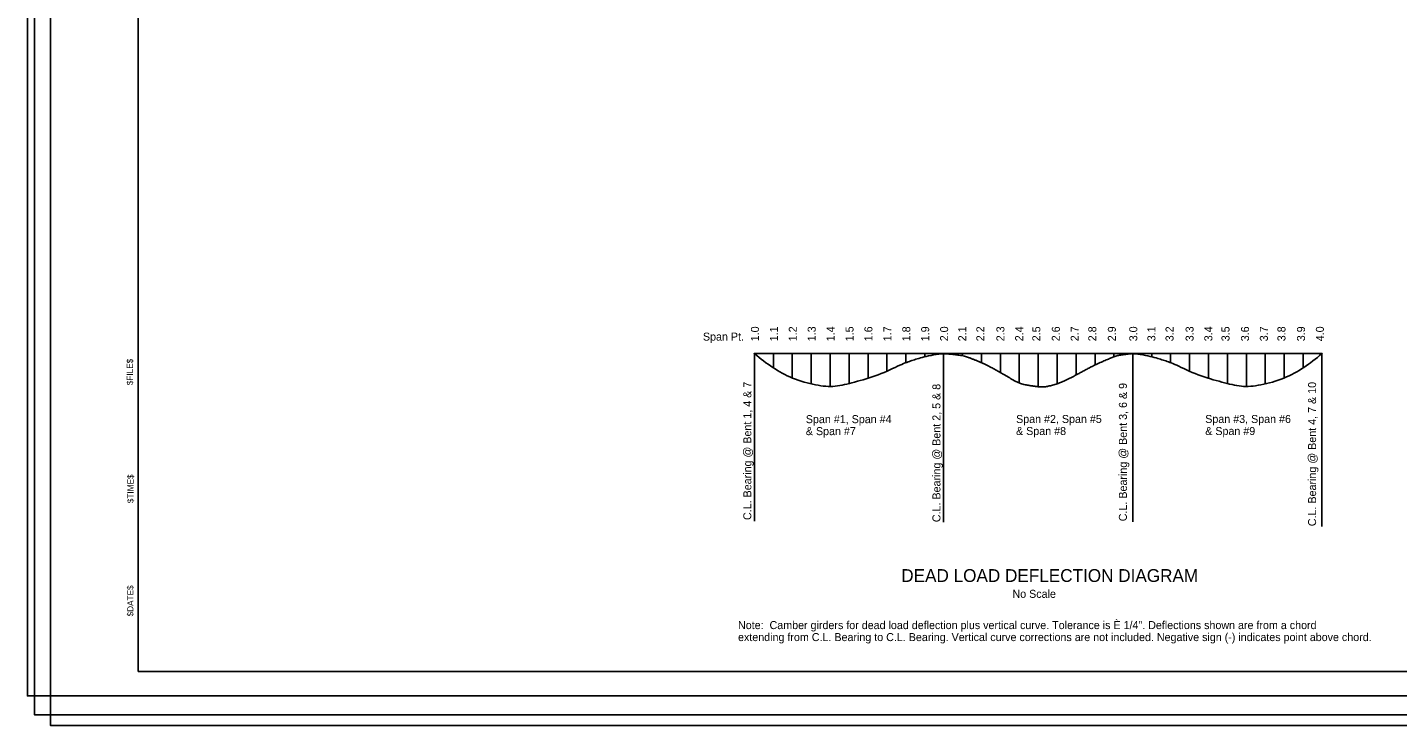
# Model space of a CAD drawing. Extents: x -725.7 to -683.7, y 85.6 to 107.6.
# Drawn here: x -725.67 to -704.28, y 85.62 to 96.51 of the extents above; entities that cross this region are included whole.
import ezdxf

# ---------------------------------------------------------------- set-up
doc = ezdxf.new("R2010")
doc.units = 0
for name, color, linetype in [('border', 7, 'Continuous'), ('Border 2660-Hwy18 - Level 62', 7, 'Continuous'), ('Border 2660-Hwy18 - Level 63', 7, 'Continuous'), ('Dimensions', 7, 'Continuous'), ('Level 20', 7, 'Continuous'), ('Level 25', 7, 'Continuous'), ('Level 40', 7, 'Continuous'), ('Level 41', 7, 'Continuous'), ('Level 62 PDF', 7, 'Continuous')]:
    doc.layers.add(name, color=color, linetype=linetype)

msp = doc.modelspace()

# ---------------------------------------------------------------- linework, layer by layer
at = {"layer": 'border'}
for p, q in [((-723.942, 86.465), (-723.942, 107.01)), ((-691.93, 86.465), (-723.942, 86.465))]:
    msp.add_line(p, q, dxfattribs=at)
at = {"layer": 'Border 2660-Hwy18 - Level 62'}
msp.add_lwpolyline([(-725.562, 107.596), (-691.443, 107.596), (-691.443, 85.786), (-725.562, 85.786)], close=True, dxfattribs=at)
at = {"layer": 'Border 2660-Hwy18 - Level 63'}
msp.add_lwpolyline([(-725.673, 107.453), (-691.673, 107.453), (-691.673, 86.083), (-725.673, 86.083)], close=True, dxfattribs=at)
at = {"layer": 'Dimensions'}
for centre in [(-714.319, 91.424), (-714.023, 91.424), (-713.728, 91.424), (-713.433, 91.424), (-713.137, 91.424), (-712.842, 91.424), (-712.546, 91.424), (-712.251, 91.424), (-711.956, 91.424), (-711.66, 91.424), (-711.365, 91.424), (-711.069, 91.424), (-710.774, 91.424), (-710.478, 91.424), (-710.183, 91.424), (-709.888, 91.424), (-709.592, 91.424), (-709.297, 91.424), (-709.001, 91.424), (-708.706, 91.424), (-708.411, 91.424), (-708.115, 91.424), (-707.82, 91.424), (-707.524, 91.424), (-707.229, 91.424), (-706.934, 91.424), (-706.638, 91.424), (-706.343, 91.424), (-706.047, 91.424), (-705.752, 91.424), (-705.457, 91.424)]:
    msp.add_circle(centre, 0.004, dxfattribs=at)
at = {"layer": 'Level 20'}
for p, q in [((-714.319, 88.808), (-714.319, 91.424)), ((-711.365, 88.793), (-711.365, 91.424)), ((-708.411, 88.8), (-708.411, 91.424)), ((-705.457, 89.939), (-705.457, 91.424)), ((-705.457, 88.728), (-705.457, 91.424))]:
    msp.add_line(p, q, dxfattribs=at)
at = {"layer": 'Level 25'}
for p, q in [((-714.319, 91.424), (-711.365, 91.424)), ((-708.411, 91.424), (-711.365, 91.424)), ((-705.457, 91.424), (-708.411, 91.424))]:
    msp.add_line(p, q, dxfattribs=at)
at = {"layer": 'Level 41'}
for p, q in [((-714.023, 91.424), (-714.023, 91.202)), ((-713.728, 91.424), (-713.728, 91.044)), ((-713.433, 91.424), (-713.433, 90.952)), ((-713.137, 91.424), (-713.137, 90.912)), ((-712.842, 91.424), (-712.842, 90.958)), ((-712.546, 91.424), (-712.546, 91.04)), ((-712.251, 91.424), (-712.251, 91.15)), ((-711.956, 91.424), (-711.956, 91.282)), ((-711.66, 91.424), (-711.66, 91.375)), ((-711.069, 91.424), (-711.069, 91.387)), ((-710.774, 91.424), (-710.774, 91.282)), ((-710.479, 91.424), (-710.479, 91.129)), ((-710.183, 91.424), (-710.183, 90.972)), ((-709.888, 91.424), (-709.888, 90.909)), ((-709.592, 91.424), (-709.592, 90.956)), ((-709.297, 91.424), (-709.297, 91.091)), ((-709.001, 91.424), (-709.001, 91.245)), ((-708.706, 91.424), (-708.706, 91.372)), ((-708.115, 91.424), (-708.115, 91.375)), ((-707.82, 91.424), (-707.82, 91.282)), ((-707.524, 91.424), (-707.524, 91.15)), ((-707.229, 91.424), (-707.229, 91.04)), ((-706.934, 91.424), (-706.934, 90.958)), ((-706.638, 91.424), (-706.638, 90.912)), ((-706.343, 91.424), (-706.343, 90.952)), ((-706.047, 91.424), (-706.047, 91.044)), ((-705.752, 91.424), (-705.752, 91.202))]:
    msp.add_line(p, q, dxfattribs=at)
for points, degree in [([(-714.317, 91.424), (-714.224, 91.342), (-714.036, 91.202), (-713.741, 91.032), (-713.347, 90.924), (-713.06, 90.898), (-712.773, 90.977), (-712.382, 91.081), (-712.016, 91.264), (-711.86, 91.316), (-711.703, 91.368), (-711.464, 91.419), (-711.365, 91.423)], 3), ([(-711.365, 91.423), (-711.09, 91.407), (-710.881, 91.329), (-710.698, 91.251), (-710.437, 91.107), (-710.176, 90.95), (-709.928, 90.911), (-709.784, 90.898), (-709.51, 90.977), (-709.315, 91.081), (-709.001, 91.251), (-708.727, 91.368), (-708.61, 91.407), (-708.411, 91.424)], 2), ([(-705.459, 91.424), (-705.551, 91.342), (-705.74, 91.202), (-706.035, 91.032), (-706.428, 90.924), (-706.716, 90.898), (-707.003, 90.977), (-707.394, 91.081), (-707.76, 91.264), (-707.916, 91.316), (-708.073, 91.368), (-708.312, 91.419), (-708.411, 91.423)], 3)]:
    msp.add_open_spline(points, degree=degree, dxfattribs=at)
at = {"layer": 'Level 62 PDF'}
msp.add_lwpolyline([(-725.312, 107.429), (-691.193, 107.429), (-691.193, 85.62), (-725.312, 85.62)], close=True, dxfattribs=at)

# ---------------------------------------------------------------- texts
at = {"layer": 'border'}
for s, p in [('$FILE$', (-724.025, 90.931)), ('$TIME$', (-724.015, 89.09)), ('$DATE$', (-724.018, 87.323))]:
    msp.add_text(s, height=0.096, rotation=89.9999, dxfattribs=at).set_placement(p)
at = {"layer": 'Level 40'}
for s, height, rotation, p in [('1.0', 0.125, 89.9998, (-714.249, 91.617)), ('1.1', 0.125, 89.9998, (-713.954, 91.617)), ('1.2', 0.125, 89.9998, (-713.658, 91.617)), ('1.3', 0.125, 89.9998, (-713.363, 91.617)), ('1.4', 0.125, 89.9998, (-713.068, 91.617)), ('1.5', 0.125, 89.9998, (-712.772, 91.617)), ('1.6', 0.125, 89.9998, (-712.477, 91.617)), ('1.7', 0.125, 89.9998, (-712.181, 91.617)), ('1.8', 0.125, 89.9998, (-711.886, 91.617)), ('1.9', 0.125, 89.9998, (-711.591, 91.617)), ('2.0', 0.125, 89.9998, (-711.295, 91.617)), ('2.1', 0.125, 89.9998, (-711.012, 91.617)), ('2.2', 0.125, 89.9998, (-710.729, 91.617)), ('2.3', 0.125, 89.9998, (-710.416, 91.617)), ('2.4', 0.125, 89.9998, (-710.123, 91.617)), ('2.5', 0.125, 89.9998, (-709.855, 91.617)), ('2.6', 0.125, 89.9998, (-709.551, 91.617)), ('2.7', 0.125, 89.9998, (-709.256, 91.617)), ('2.8', 0.125, 89.9998, (-708.981, 91.617)), ('2.9', 0.125, 89.9998, (-708.676, 91.617)), ('3.0', 0.125, 89.9998, (-708.341, 91.617)), ('3.1', 0.125, 89.9998, (-708.058, 91.617)), ('3.2', 0.125, 89.9998, (-707.775, 91.617)), ('3.3', 0.125, 89.9998, (-707.462, 91.617)), ('3.4', 0.125, 89.9998, (-707.169, 91.617)), ('3.5', 0.125, 89.9998, (-706.901, 91.617)), ('3.6', 0.125, 89.9998, (-706.596, 91.617)), ('3.7', 0.125, 89.9998, (-706.302, 91.617)), ('3.8', 0.125, 89.9998, (-706.027, 91.617)), ('3.9', 0.125, 89.9998, (-705.722, 91.617)), ('4.0', 0.125, 89.9998, (-705.427, 91.617)), ('Span Pt.', 0.125, 359.9998, (-715.124, 91.627)), ('C.L. Bearing @ Bent 1, 4 & 7', 0.12501, 89.9998, (-714.368, 88.827)), ('C.L. Bearing @ Bent 2, 5 & 8', 0.12501, 89.9998, (-711.415, 88.794)), ('C.L. Bearing @ Bent 3, 6 & 9', 0.12501, 89.9998, (-708.503, 88.808)), ('C.L. Bearing @ Bent 4, 7 & 10', 0.12501, 89.9998, (-705.549, 88.731)), ('Span #1, Span #4', 0.12501, 359.9998, (-713.517, 90.339)), ('Span #2, Span #5', 0.12501, 359.9998, (-710.234, 90.342)), ('Span #3, Span #6', 0.12501, 359.9998, (-707.28, 90.342)), ('& Span #7', 0.125, 359.9998, (-713.517, 90.152)), ('& Span #8', 0.125, 359.9998, (-710.234, 90.154)), ('& Span #9', 0.125, 359.9998, (-707.28, 90.154))]:
    msp.add_text(s, height=height, rotation=rotation, dxfattribs=at).set_placement(p)
for s, p in [('No Scale', (-710.29, 87.613)), ('Note:  Camber girders for dead load deflection plus vertical curve. Tolerance is È 1/4". Deflections shown are from a chord', (-714.576, 87.125)), ('extending from C.L. Bearing to C.L. Bearing. Vertical curve corrections are not included. Negative sign (-) indicates point above chord.', (-714.576, 86.938))]:
    msp.add_text(s, height=0.125, dxfattribs=at).set_placement(p)
at = {"layer": 'Level 41'}
msp.add_text(' DEAD LOAD DEFLECTION DIAGRAM ', height=0.2, dxfattribs=at).set_placement((-712.101, 87.861))

doc.saveas('drawing.dxf')
